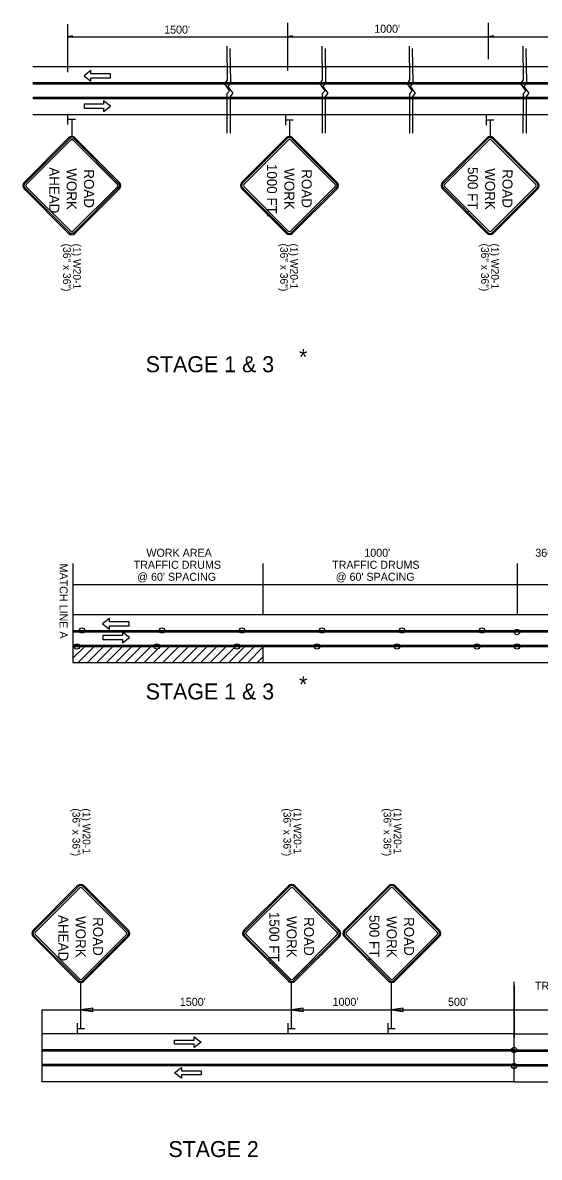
# Model space of a CAD drawing. Extents: x 1930579 to 1946213, y 596452 to 597784.
# Drawn here: x 1936400 to 1936788, y 596725 to 597575 of the extents above; entities that cross this region are included whole.
import ezdxf

# ---------------------------------------------------------------- set-up
doc = ezdxf.new("R2010")
doc.units = 0
for name, color, linetype in [('Default', 7, 'Continuous'), ('P_TC_Signs_Temporary', 7, 'Continuous'), ('R_Border', 7, 'Continuous'), ('R_Striping', 7, 'Continuous')]:
    doc.layers.add(name, color=color, linetype=linetype)

msp = doc.modelspace()

# ---------------------------------------------------------------- linework, layer by layer
at = {"layer": 'Default'}
for p, q in [((1936433.73, 597574.01), (1936433.73, 597538.1)), ((1936598.64, 597575.24), (1936598.64, 597539.32)), ((1936749.27, 597575.24), (1936749.27, 597547.85)), ((1936437.56, 597565.28), (1936433.73, 597564.71)), ((1936433.73, 597564.71), (1936598.64, 597564.71)), ((1936437.56, 597564.13), (1936433.73, 597564.71)), ((1936437.56, 597565.19), (1936434.37, 597564.71)), ((1936437.56, 597564.23), (1936434.37, 597564.71)), ((1936437.56, 597565.09), (1936435.03, 597564.71)), ((1936437.56, 597564.33), (1936435.03, 597564.71)), ((1936437.56, 597564.99), (1936435.67, 597564.71)), ((1936437.56, 597564.42), (1936435.67, 597564.71)), ((1936437.56, 597564.89), (1936436.32, 597564.71)), ((1936437.56, 597564.52), (1936436.32, 597564.71)), ((1936437.56, 597564.8), (1936436.95, 597564.71)), ((1936437.56, 597564.62), (1936436.95, 597564.71)), ((1936437.56, 597564.13), (1936437.56, 597565.28)), ((1936602.46, 597565.28), (1936598.64, 597564.71)), ((1936602.46, 597565.28), (1936598.64, 597564.71)), ((1936598.64, 597564.71), (1936749.27, 597564.71)), ((1936602.46, 597564.13), (1936598.64, 597564.71)), ((1936602.46, 597564.13), (1936598.64, 597564.71)), ((1936602.46, 597565.19), (1936599.28, 597564.71)), ((1936602.46, 597565.19), (1936599.28, 597564.71)), ((1936602.46, 597564.23), (1936599.28, 597564.71)), ((1936602.46, 597564.23), (1936599.28, 597564.71)), ((1936602.46, 597565.09), (1936599.93, 597564.71)), ((1936602.46, 597565.09), (1936599.93, 597564.71)), ((1936602.46, 597564.33), (1936599.93, 597564.71)), ((1936602.46, 597564.33), (1936599.93, 597564.71)), ((1936602.46, 597564.99), (1936600.57, 597564.71)), ((1936602.46, 597564.99), (1936600.57, 597564.71)), ((1936602.46, 597564.42), (1936600.57, 597564.71)), ((1936602.46, 597564.42), (1936600.57, 597564.71)), ((1936602.46, 597564.89), (1936601.22, 597564.71)), ((1936602.46, 597564.89), (1936601.22, 597564.71)), ((1936602.46, 597564.52), (1936601.22, 597564.71)), ((1936602.46, 597564.52), (1936601.22, 597564.71)), ((1936602.46, 597564.8), (1936601.86, 597564.71)), ((1936602.46, 597564.8), (1936601.86, 597564.71)), ((1936602.46, 597564.62), (1936601.86, 597564.71)), ((1936602.46, 597564.62), (1936601.86, 597564.71)), ((1936602.46, 597564.13), (1936602.46, 597565.28)), ((1936602.46, 597564.13), (1936602.46, 597565.28)), ((1936753.1, 597565.28), (1936749.27, 597564.71)), ((1936749.27, 597564.71), (1936936.62, 597564.71)), ((1936753.1, 597564.13), (1936749.27, 597564.71)), ((1936753.1, 597565.19), (1936749.91, 597564.71)), ((1936753.1, 597564.23), (1936749.91, 597564.71)), ((1936753.1, 597565.09), (1936750.57, 597564.71)), ((1936753.1, 597564.33), (1936750.57, 597564.71)), ((1936753.1, 597564.99), (1936751.21, 597564.71)), ((1936753.1, 597564.42), (1936751.21, 597564.71)), ((1936753.1, 597564.89), (1936751.86, 597564.71)), ((1936753.1, 597564.52), (1936751.86, 597564.71)), ((1936753.1, 597564.8), (1936752.49, 597564.71)), ((1936753.1, 597564.62), (1936752.49, 597564.71)), ((1936753.1, 597564.13), (1936753.1, 597565.28)), ((1936407.68, 597542.47), (1937340.86, 597542.47)), ((1936407.68, 597530.47), (1937340.86, 597530.47)), ((1936407.68, 597529.47), (1937340.86, 597529.47)), ((1936407.68, 597519.47), (1937340.86, 597519.47)), ((1936407.68, 597518.47), (1937340.86, 597518.47)), ((1936407.68, 597506.47), (1937340.86, 597506.47)), ((1936434.02, 597498.85), (1936434.02, 597506.83)), ((1936434.14, 597502.81), (1936439.59, 597502.81)), ((1936597.31, 597498.34), (1936597.31, 597506.32)), ((1936597.43, 597502.31), (1936602.87, 597502.31)), ((1936747.89, 597498.34), (1936747.89, 597506.32)), ((1936748, 597502.31), (1936753.45, 597502.31)), ((1936437.73, 597169.77), (1936437.73, 597095.65)), ((1936580.29, 597169.77), (1936580.29, 597131.65)), ((1936770.82, 597169.77), (1936770.82, 597131.65)), ((1936770.82, 597153.89), (1936437.73, 597153.89)), ((1936984.52, 597153.89), (1936770.82, 597153.89)), ((1936437.73, 597131.65), (1937437.73, 597131.65)), ((1936437.73, 597119.65), (1937437.73, 597119.65)), ((1936437.73, 597119.65), (1936984.52, 597119.65)), ((1936437.73, 597118.65), (1937437.73, 597118.65)), ((1936437.73, 597108.65), (1937437.73, 597108.65)), ((1936437.73, 597107.65), (1937437.73, 597107.65)), ((1936437.73, 597098.81), (1936446.58, 597107.65)), ((1936441.65, 597095.65), (1936453.65, 597107.65)), ((1936448.73, 597095.65), (1936460.73, 597107.65)), ((1936455.8, 597095.65), (1936467.8, 597107.65)), ((1936462.87, 597095.65), (1936474.87, 597107.65)), ((1936469.94, 597095.65), (1936481.94, 597107.65)), ((1936477.01, 597095.65), (1936489.01, 597107.65)), ((1936484.08, 597095.65), (1936496.08, 597107.65)), ((1936491.15, 597095.65), (1936503.15, 597107.65)), ((1936498.22, 597095.65), (1936510.22, 597107.65)), ((1936505.29, 597095.65), (1936517.29, 597107.65)), ((1936512.37, 597095.65), (1936524.37, 597107.65)), ((1936519.44, 597095.65), (1936531.44, 597107.65)), ((1936526.51, 597095.65), (1936538.51, 597107.65)), ((1936533.58, 597095.65), (1936545.58, 597107.65)), ((1936540.65, 597095.65), (1936552.65, 597107.65)), ((1936547.72, 597095.65), (1936559.72, 597107.65)), ((1936554.79, 597095.65), (1936566.5, 597107.36)), ((1936561.86, 597095.65), (1936573.86, 597107.65)), ((1936568.93, 597095.65), (1936580.29, 597107.01)), ((1936580.29, 597107.65), (1936580.29, 597095.65)), ((1936437.73, 597095.65), (1937437.73, 597095.65)), ((1936576, 597095.65), (1936580.29, 597099.94)), ((1936768.61, 596781.24), (1936768.61, 596856.24)), ((1936768.61, 596853.31), (1936768.61, 596814.31)), ((1936414.51, 596835.27), (1936768.61, 596835.27)), ((1936414.51, 596835.27), (1936414.51, 596781.24)), ((1936452.58, 596836.6), (1936443.72, 596835.27)), ((1936443.72, 596835.27), (1936452.58, 596833.94)), ((1936452.58, 596833.94), (1936452.58, 596836.6)), ((1936610.52, 596836.6), (1936601.65, 596835.27)), ((1936601.65, 596835.27), (1936610.52, 596833.94)), ((1936610.52, 596833.94), (1936610.52, 596836.6)), ((1936685.47, 596836.6), (1936676.61, 596835.27)), ((1936676.61, 596835.27), (1936685.47, 596833.94)), ((1936685.47, 596833.94), (1936685.47, 596836.6)), ((1936768.61, 596835.27), (1936868.61, 596835.27)), ((1936441, 596825.22), (1936441, 596817.24)), ((1936441.12, 596821.25), (1936446.57, 596821.25)), ((1936598.93, 596825.22), (1936598.93, 596817.24)), ((1936599.05, 596821.25), (1936604.5, 596821.25)), ((1936673.89, 596825.22), (1936673.89, 596817.24)), ((1936674.01, 596821.25), (1936679.46, 596821.25)), ((1936768.61, 596817.24), (1936414.51, 596817.24)), ((1936768.61, 596817.24), (1936868.61, 596817.24)), ((1936768.61, 596805.24), (1936414.51, 596805.24)), ((1936768.61, 596804.24), (1936414.51, 596804.24)), ((1936768.61, 596805.24), (1936868.61, 596805.24)), ((1936768.61, 596804.24), (1936868.61, 596804.24)), ((1936768.61, 596794.24), (1936414.51, 596794.24)), ((1936768.61, 596793.24), (1936414.51, 596793.24)), ((1936768.61, 596794.24), (1936868.61, 596794.24)), ((1936768.61, 596793.24), (1936868.61, 596793.24)), ((1936768.61, 596781.24), (1936414.51, 596781.24)), ((1936768.61, 596781.24), (1936868.61, 596781.24))]:
    msp.add_line(p, q, dxfattribs=at)
for points in [[(1936553.06, 597557.58), (1936553.44, 597532.34), (1936551.49, 597529.45), (1936555.29, 597524.25), (1936553.29, 597521.85), (1936553.28, 597492.5)], [(1936555.45, 597555.98), (1936555.84, 597530.42), (1936553.89, 597527.52), (1936557.69, 597522.32), (1936555.69, 597519.92), (1936555.68, 597492.36)], [(1936624.42, 597557.58), (1936624.8, 597532.34), (1936622.86, 597529.45), (1936626.65, 597524.25), (1936624.65, 597521.85), (1936624.65, 597492.5)], [(1936626.81, 597555.98), (1936627.2, 597530.42), (1936625.25, 597527.52), (1936629.05, 597522.32), (1936627.05, 597519.92), (1936627.05, 597492.36)], [(1936689.86, 597557.58), (1936690.25, 597532.34), (1936688.3, 597529.45), (1936692.1, 597524.25), (1936690.1, 597521.85), (1936690.09, 597492.5)], [(1936692.26, 597555.98), (1936692.64, 597530.42), (1936690.7, 597527.52), (1936694.49, 597522.32), (1936692.49, 597519.92), (1936692.49, 597492.36)], [(1936775.06, 597557.58), (1936775.44, 597532.34), (1936773.49, 597529.45), (1936777.29, 597524.25), (1936775.29, 597521.85), (1936775.28, 597492.5)], [(1936777.45, 597555.98), (1936777.84, 597530.42), (1936775.89, 597527.52), (1936779.69, 597522.32), (1936777.69, 597519.92), (1936777.68, 597492.36)]]:
    msp.add_lwpolyline(points, dxfattribs=at)
for centre in [(1936444.52, 597119.65), (1936504.52, 597119.65), (1936564.52, 597119.65), (1936624.52, 597119.65), (1936684.52, 597119.65), (1936744.51, 597119.65), (1936770.78, 597118.45), (1936440.77, 597107.65), (1936500.77, 597107.65), (1936560.77, 597107.65), (1936620.77, 597107.65), (1936680.77, 597107.65), (1936740.77, 597107.65), (1936770.82, 597107.65), (1936768.61, 596805.24), (1936768.61, 596793.24)]:
    msp.add_circle(centre, 1.99, dxfattribs=at)
at = {"layer": 'P_TC_Signs_Temporary'}
for p, q in [((1936401.07, 597455.49), (1936434.48, 597488.9)), ((1936401.73, 597454.82), (1936435.14, 597488.23)), ((1936402.66, 597453.9), (1936436.07, 597487.31)), ((1936437.66, 597487.31), (1936471.07, 597453.9)), ((1936438.59, 597488.23), (1936472, 597454.82)), ((1936439.25, 597488.9), (1936472.66, 597455.49)), ((1936564.31, 597455.6), (1936597.76, 597488.97)), ((1936564.97, 597454.94), (1936598.42, 597488.31)), ((1936565.9, 597454.01), (1936599.35, 597487.38)), ((1936600.94, 597487.38), (1936634.31, 597453.93)), ((1936601.87, 597488.3), (1936635.24, 597454.85)), ((1936602.53, 597488.97), (1936635.9, 597455.51)), ((1936714.9, 597455.59), (1936748.34, 597488.97)), ((1936715.57, 597454.92), (1936749, 597488.31)), ((1936716.49, 597453.99), (1936749.93, 597487.38)), ((1936751.52, 597487.38), (1936784.91, 597453.94)), ((1936752.45, 597488.31), (1936785.84, 597454.87)), ((1936753.11, 597488.97), (1936786.5, 597455.53)), ((1936434.48, 597417.3), (1936401.07, 597450.71)), ((1936435.14, 597417.97), (1936401.73, 597451.38)), ((1936436.07, 597418.89), (1936402.66, 597452.3)), ((1936471.07, 597452.3), (1936437.66, 597418.89)), ((1936472, 597451.38), (1936438.59, 597417.97)), ((1936472.66, 597450.71), (1936439.25, 597417.3)), ((1936597.67, 597417.38), (1936564.3, 597450.83)), ((1936598.34, 597418.04), (1936564.97, 597451.49)), ((1936599.27, 597418.97), (1936565.9, 597452.42)), ((1936634.31, 597452.33), (1936600.86, 597418.96)), ((1936635.24, 597451.41), (1936601.78, 597418.04)), ((1936635.9, 597450.74), (1936602.45, 597417.37)), ((1936748.29, 597417.38), (1936714.9, 597450.81)), ((1936748.95, 597418.04), (1936715.56, 597451.47)), ((1936749.88, 597418.97), (1936716.49, 597452.4)), ((1936784.91, 597452.35), (1936751.47, 597418.97)), ((1936785.83, 597451.42), (1936752.4, 597418.04)), ((1936786.5, 597450.76), (1936753.06, 597417.37)), ((1936407.85, 596894.94), (1936441.26, 596928.35)), ((1936408.51, 596894.28), (1936441.92, 596927.69)), ((1936409.44, 596893.35), (1936442.85, 596926.76)), ((1936444.44, 596926.76), (1936477.85, 596893.35)), ((1936445.37, 596927.69), (1936478.78, 596894.28)), ((1936446.03, 596928.35), (1936479.44, 596894.94)), ((1936566.04, 596894.96), (1936599.49, 596928.33)), ((1936566.7, 596894.3), (1936600.15, 596927.67)), ((1936567.63, 596893.37), (1936601.08, 596926.74)), ((1936602.67, 596926.74), (1936636.04, 596893.29)), ((1936603.6, 596927.67), (1936636.97, 596894.21)), ((1936604.26, 596928.33), (1936637.63, 596894.88)), ((1936641.12, 596894.95), (1936674.55, 596928.33)), ((1936641.78, 596894.28), (1936675.21, 596927.67)), ((1936642.71, 596893.35), (1936676.14, 596926.74)), ((1936677.73, 596926.74), (1936711.12, 596893.3)), ((1936678.66, 596927.67), (1936712.05, 596894.23)), ((1936679.32, 596928.33), (1936712.71, 596894.89)), ((1936441.26, 596856.75), (1936407.85, 596890.17)), ((1936441.92, 596857.42), (1936408.51, 596890.83)), ((1936442.85, 596858.35), (1936409.44, 596891.76)), ((1936477.85, 596891.76), (1936444.44, 596858.35)), ((1936478.78, 596890.83), (1936445.37, 596857.42)), ((1936479.44, 596890.17), (1936446.03, 596856.75)), ((1936599.4, 596856.74), (1936566.03, 596890.19)), ((1936600.06, 596857.4), (1936566.69, 596890.85)), ((1936600.99, 596858.33), (1936567.62, 596891.78)), ((1936636.04, 596891.7), (1936602.58, 596858.33)), ((1936636.96, 596890.77), (1936603.51, 596857.4)), ((1936637.63, 596890.1), (1936604.17, 596856.73)), ((1936674.5, 596856.74), (1936641.11, 596890.17)), ((1936675.16, 596857.4), (1936641.78, 596890.84)), ((1936676.09, 596858.33), (1936642.7, 596891.76)), ((1936711.12, 596891.71), (1936677.68, 596858.33)), ((1936712.04, 596890.78), (1936678.61, 596857.4)), ((1936712.71, 596890.12), (1936679.27, 596856.73))]:
    msp.add_line(p, q, dxfattribs=at)
for centre, radius, start, end in [((1936436.86, 597486.51), 3.38, 45, 135), ((1936436.86, 597486.51), 2.44, 45, 135), ((1936436.86, 597486.51), 1.12, 45, 135), ((1936600.15, 597486.58), 3.37, 44.93005, 134.93005), ((1936600.15, 597486.58), 2.44, 44.93005, 134.93005), ((1936600.15, 597486.58), 1.12, 44.93005, 134.93005), ((1936750.73, 597486.58), 3.37, 44.9574, 134.9574), ((1936750.73, 597486.58), 2.44, 44.9574, 134.9574), ((1936750.73, 597486.58), 1.12, 44.9574, 134.9574), ((1936403.45, 597453.1), 3.37, 135, 225), ((1936403.45, 597453.1), 2.44, 135, 225), ((1936403.45, 597453.1), 1.13, 135, 225), ((1936470.27, 597453.1), 1.13, 315, 45), ((1936470.27, 597453.1), 2.44, 315, 45), ((1936470.27, 597453.1), 3.38, 315, 45), ((1936566.69, 597453.21), 3.37, 134.93005, 224.93005), ((1936566.69, 597453.21), 2.44, 134.93005, 224.93005), ((1936566.69, 597453.21), 1.13, 134.93005, 224.93005), ((1936633.52, 597453.13), 1.13, 314.93005, 44.93005), ((1936633.52, 597453.13), 2.44, 314.93005, 44.93005), ((1936633.52, 597453.13), 3.38, 314.93005, 44.93005), ((1936717.29, 597453.2), 3.37, 134.9574, 224.9574), ((1936717.29, 597453.2), 2.44, 134.9574, 224.9574), ((1936717.29, 597453.2), 1.13, 134.9574, 224.9574), ((1936784.11, 597453.15), 1.13, 314.9574, 44.9574), ((1936784.11, 597453.15), 2.44, 314.9574, 44.9574), ((1936784.11, 597453.15), 3.37, 314.9574, 44.9574), ((1936436.86, 597419.69), 3.38, 225, 315), ((1936436.86, 597419.69), 2.44, 225, 315), ((1936436.86, 597419.69), 1.12, 225, 315), ((1936600.06, 597419.76), 3.37, 224.93005, 314.93005), ((1936600.06, 597419.76), 2.44, 224.93005, 314.93005), ((1936600.06, 597419.76), 1.12, 224.93005, 314.93005), ((1936750.68, 597419.76), 3.37, 224.9574, 314.9574), ((1936750.68, 597419.76), 2.44, 224.9574, 314.9574), ((1936750.68, 597419.76), 1.12, 224.9574, 314.9574), ((1936443.64, 596925.96), 3.38, 45, 135), ((1936443.64, 596925.96), 2.44, 45, 135), ((1936443.64, 596925.96), 1.12, 45, 135), ((1936601.87, 596925.94), 3.37, 44.93005, 134.93005), ((1936601.87, 596925.94), 2.44, 44.93005, 134.93005), ((1936601.87, 596925.94), 1.12, 44.93005, 134.93005), ((1936676.94, 596925.94), 3.37, 44.9574, 134.9574), ((1936676.94, 596925.94), 2.44, 44.9574, 134.9574), ((1936676.94, 596925.94), 1.12, 44.9574, 134.9574), ((1936410.23, 596892.55), 3.37, 135, 225), ((1936410.23, 596892.55), 2.44, 135, 225), ((1936410.23, 596892.55), 1.13, 135, 225), ((1936477.05, 596892.55), 1.13, 315, 45), ((1936477.05, 596892.55), 2.44, 315, 45), ((1936477.05, 596892.55), 3.38, 315, 45), ((1936568.42, 596892.57), 3.37, 134.93005, 224.93005), ((1936568.42, 596892.57), 2.44, 134.93005, 224.93005), ((1936568.42, 596892.57), 1.13, 134.93005, 224.93005), ((1936635.24, 596892.49), 1.13, 314.93005, 44.93005), ((1936635.24, 596892.49), 2.44, 314.93005, 44.93005), ((1936635.24, 596892.49), 3.38, 314.93005, 44.93005), ((1936643.5, 596892.56), 3.37, 134.9574, 224.9574), ((1936643.5, 596892.56), 2.44, 134.9574, 224.9574), ((1936643.5, 596892.56), 1.13, 134.9574, 224.9574), ((1936710.32, 596892.51), 1.13, 314.9574, 44.9574), ((1936710.32, 596892.51), 2.44, 314.9574, 44.9574), ((1936710.32, 596892.51), 3.37, 314.9574, 44.9574), ((1936443.64, 596859.14), 3.38, 225, 315), ((1936443.64, 596859.14), 2.44, 225, 315), ((1936443.64, 596859.14), 1.12, 225, 315), ((1936601.79, 596859.12), 3.37, 224.93005, 314.93005), ((1936601.79, 596859.12), 2.44, 224.93005, 314.93005), ((1936601.79, 596859.12), 1.12, 224.93005, 314.93005), ((1936676.89, 596859.12), 3.37, 224.9574, 314.9574), ((1936676.89, 596859.12), 2.44, 224.9574, 314.9574), ((1936676.89, 596859.12), 1.12, 224.9574, 314.9574)]:
    msp.add_arc(centre, radius, start, end, dxfattribs=at)
at = {"layer": 'R_Border'}
for p, q in [((1936436.86, 597502.81), (1936436.86, 597489.89)), ((1936600.15, 597502.31), (1936600.15, 597489.96)), ((1936750.73, 597502.31), (1936750.73, 597489.96)), ((1936443.59, 596821.25), (1936443.64, 596855.77)), ((1936601.65, 596821.25), (1936601.7, 596855.77)), ((1936676.73, 596821.25), (1936676.78, 596855.77))]:
    msp.add_line(p, q, dxfattribs=at)
at = {"layer": 'R_Striping'}
for points in [[(1936451.26, 597539.49), (1936446.07, 597535.49), (1936451.26, 597531.49), (1936451.26, 597533.99), (1936465.97, 597533.99), (1936465.97, 597536.99), (1936451.26, 597536.99)], [(1936460.78, 597508.67), (1936465.97, 597512.67), (1936460.78, 597516.67), (1936460.78, 597514.17), (1936446.07, 597514.17), (1936446.07, 597511.17), (1936460.78, 597511.17)], [(1936465.14, 597128.67), (1936459.95, 597124.67), (1936465.14, 597120.67), (1936465.14, 597123.17), (1936479.85, 597123.17), (1936479.85, 597126.17), (1936465.14, 597126.17)], [(1936474.88, 597110.32), (1936480.08, 597114.32), (1936474.88, 597118.32), (1936474.88, 597115.82), (1936460.17, 597115.82), (1936460.17, 597112.82), (1936474.88, 597112.82)], [(1936528.65, 596814.96), (1936533.84, 596810.96), (1936528.65, 596806.96), (1936528.65, 596809.46), (1936513.93, 596809.46), (1936513.93, 596812.46), (1936528.65, 596812.46)], [(1936519.13, 596784.15), (1936513.93, 596788.15), (1936519.13, 596792.15), (1936519.13, 596789.65), (1936533.84, 596789.65), (1936533.84, 596786.65), (1936519.13, 596786.65)]]:
    msp.add_lwpolyline(points, close=True, dxfattribs=at)

# ---------------------------------------------------------------- texts
at = {"layer": 'Default'}
for s, height, p in [("1500'", 6, (1936506.17, 597567.03)), ('STAGE 1 & 3', 12, (1936492.34, 597313.22)), ('*', 12, (1936607.32, 597318.66)), ('*', 12, (1936607.32, 597073.35)), ('STAGE 1 & 3', 12, (1936492.34, 597067.92)), ('TRAFFIC DRUMS ', 6, (1936784.27, 596850.27)), ('STAGE 2', 12, (1936509.35, 596724.9))]:
    msp.add_text(s, height=height, dxfattribs=at).set_placement(p)
for s, rotation, p in [("1000'", 0, (1936663.7, 597567.71)), ('WORK AREA', 360, (1936492.86, 597174.89)), ("1000'", 360, (1936656.27, 597174.89)), ("360' EXIT TAPER FOR LANE CLOSURE", 360, (1936784.5, 597174.89)), ('TRAFFIC DRUMS', 360, (1936483.29, 597165.89)), ('TRAFFIC DRUMS ', 360, (1936632.17, 597165.89)), ('MATCH LINE A', 270, (1936427.76, 597169.77)), ("@ 60' SPACING", 360, (1936485.96, 597156.89)), ("@ 60' SPACING", 360, (1936634.84, 597156.89)), ("1500'", 0, (1936517.95, 596838.27)), ("1000'", 0, (1936632.47, 596838.27)), ("500'", 0, (1936719.07, 596838.27))]:
    msp.add_text(s, height=6, rotation=rotation, dxfattribs=at).set_placement(p)
at = {"layer": 'P_TC_Signs_Temporary'}
for s, rotation, p in [('1000 FT.', 269.93005, (1936583.29, 597469.37)), (' AHEAD ', 270, (1936420.03, 597469.64)), ('WORK', 270, (1936433.05, 597466.09)), (' ROAD ', 270, (1936446.08, 597468.12)), ('WORK', 269.93005, (1936596.31, 597466.17)), (' ROAD ', 269.93005, (1936609.34, 597468.18)), ('500 FT.', 269.9574, (1936733.88, 597467.03)), ('WORK', 269.9574, (1936746.9, 597466.16)), (' ROAD ', 269.9574, (1936759.92, 597468.19)), (' AHEAD ', 270, (1936426.81, 596909.09)), ('1500 FT.', 269.93005, (1936585.02, 596908.73)), ('WORK', 270, (1936439.83, 596905.54)), (' ROAD ', 270, (1936452.86, 596907.57)), ('WORK', 269.93005, (1936598.04, 596905.53)), (' ROAD ', 269.93005, (1936611.06, 596907.54)), ('500 FT.', 269.9574, (1936660.09, 596906.39)), ('WORK', 269.9574, (1936673.11, 596905.53)), (' ROAD ', 269.9574, (1936686.14, 596907.55))]:
    msp.add_text(s, height=7.5, rotation=rotation, dxfattribs=at).set_placement(p)
at = {"layer": 'R_Border'}
for s, p in [('(36" x 36")', (1936430.38, 597409.66)), ('(1) W20-1', (1936437.97, 597409.66)), ('(36" x 36")', (1936593.2, 597409.74)), ('(1) W20-1', (1936600.78, 597409.74)), ('(36" x 36")', (1936743.9, 597409.73)), ('(1) W20-1', (1936751.49, 597409.73)), ('(36" x 36")', (1936437.42, 596986.33)), ('(1) W20-1', (1936445.11, 596986.33)), ('(36" x 36")', (1936595.65, 596986.31)), ('(1) W20-1', (1936603.34, 596986.31)), ('(36" x 36")', (1936670.72, 596986.31)), ('(1) W20-1', (1936678.4, 596986.31))]:
    msp.add_text(s, height=5.76, rotation=270, dxfattribs=at).set_placement(p)

doc.saveas('drawing.dxf')
